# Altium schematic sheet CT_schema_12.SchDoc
size 274 x 160 mm
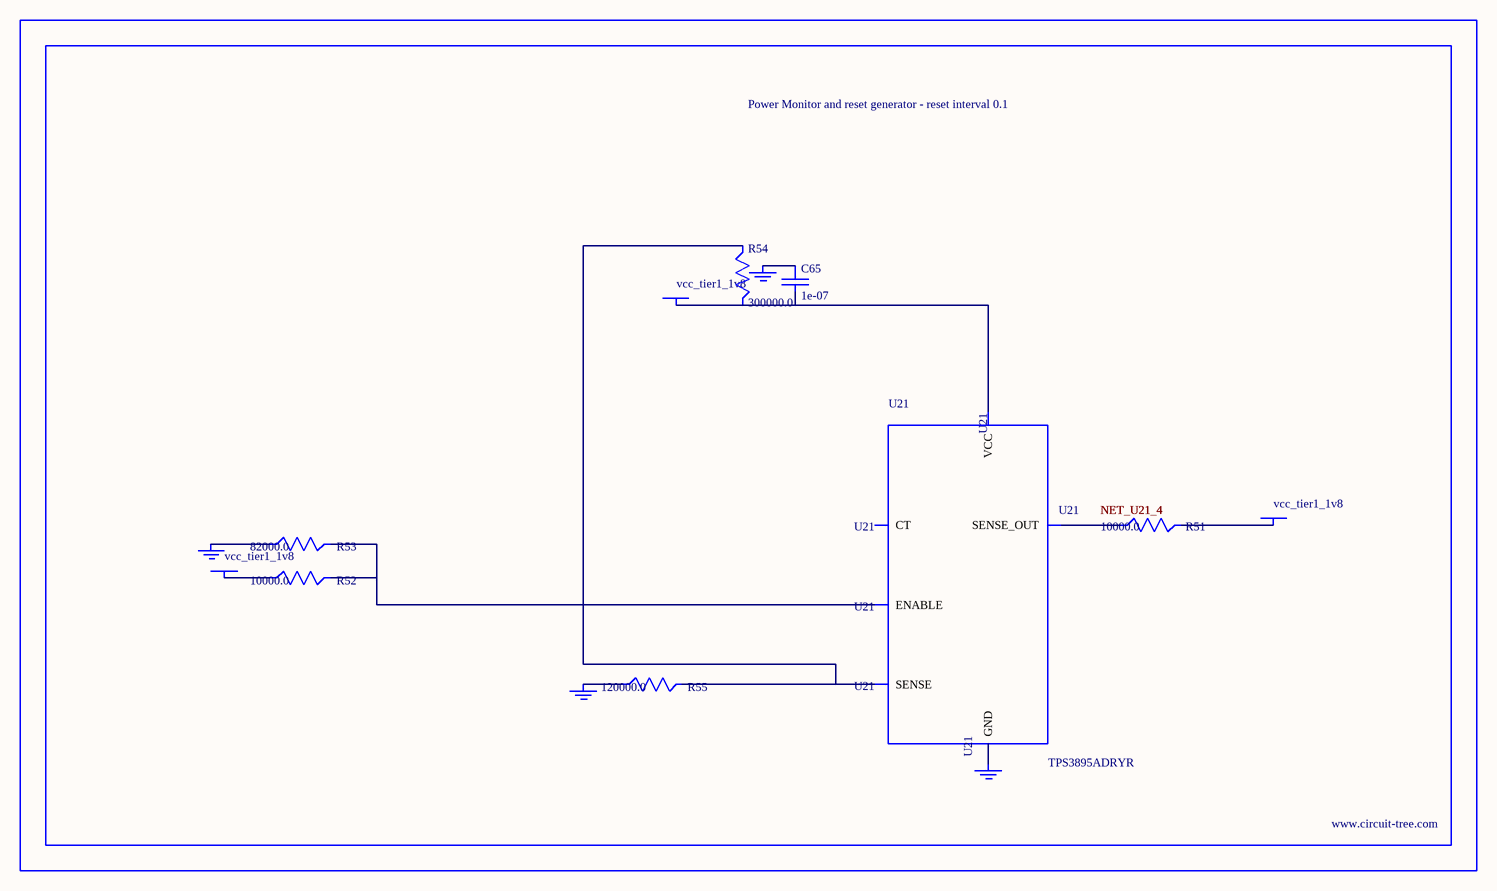
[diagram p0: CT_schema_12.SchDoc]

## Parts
BORDER11  (no value)
C65  1e-07  [C0402]
GND_INSTANCE_11_0  (no value)
GND_INSTANCE_11_1  (no value)
GND_INSTANCE_11_2  (no value)
GND_INSTANCE_11_3  (no value)
POWER_INSTANCE_11_0  vcc_tier1_1v8
POWER_INSTANCE_11_1  vcc_tier1_1v8
POWER_INSTANCE_11_2  vcc_tier1_1v8
R51  10000.0  [R0603]
R52  10000.0  [R0603]
R53  82000.0  [R0603]
R54  300000.0  [R0603]
R55  120000.0  [R0603]
U21  TPS3895ADRYR  [SON-6]

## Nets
NetC65_1: C65.1 GND_INSTANCE_11_2.0(GND)
NetC65_2: C65.2 POWER_INSTANCE_11_2.0(PWR) R54.2 U21.6(VCC)
NetGND_INSTANCE_11_0_0: GND_INSTANCE_11_0.0(GND) R53.1
NetGND_INSTANCE_11_1_0: GND_INSTANCE_11_1.0(GND) R55.1
NetGND_INSTANCE_11_3_0: GND_INSTANCE_11_3.0(GND) U21.2(GND)
NetPOWER_INSTANCE_11_0_0: POWER_INSTANCE_11_0.0(PWR) R52.1
NetPOWER_INSTANCE_11_1_0: POWER_INSTANCE_11_1.0(PWR) R51.2
NetR51_1: R51.1 U21.4(SENSE_OUT)
NetR52_2: R52.2 R53.2 U21.1(ENABLE)
NetR54_1: R54.1 R55.2 U21.3(SENSE)

Not connected (* = marked no-connect by the designer): U21 5(CT)

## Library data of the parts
BORDER11 = BORDER_PAGE11
C65 = C0402C104K3RACTU
GND_INSTANCE_11_0-GND_INSTANCE_11_3 = GND
POWER_INSTANCE_11_0-POWER_INSTANCE_11_2 = PWR
R51 R52 = RC0603JR-0710KL
R53 = RC0603JR-0782KL
R54 = RC0603JR-07300KL
R55 = RC0603JR-07120KL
